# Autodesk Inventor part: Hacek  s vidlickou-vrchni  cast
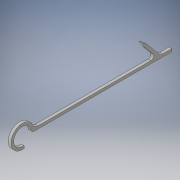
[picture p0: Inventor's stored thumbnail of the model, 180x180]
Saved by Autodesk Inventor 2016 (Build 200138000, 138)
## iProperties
Created: 2015-07
Part Number: Hacek  s vidlickou-vrchni  cast
Material: Generic
Document SubType Name: Modeling
Designer: brecka
Density: 1 g/cm^3
Appearance: Default
Author: brecka
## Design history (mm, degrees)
derived "Hacek  s vidlickou.ipt"
sketch "Náčrt1"
  geometry: L1 (186.029, 3.62)-(199.435, 13.907) reference; L2 (140.971, 3)-(184.202, 3) reference; L3 (123.869, 20.602)-(137.14, 4.786) reference; L4 (118.221, 25)-(123.869, 20.602) reference; L5 (121.571, 18.674)-(118.221, 25) reference; L6 (130.587, 7.928)-(121.571, 18.674) reference; L7 (4.502, 3)-(128.289, 3) reference; L8 (-10.734, -7.851)-(-10.204, -10.804) reference; L9 (184.202, 0)-(0, 0) reference; L10 (199.435, -10.907)-(186.029, -0.62) reference; L11 (199.08, -6.543)-(200.529, -11.436) reference; L12 (191.296, -0.88)-(197.986, -6.014) reference; L13 (197.986, 9.014)-(191.296, 3.88) reference; L14 (200.529, 14.436)-(199.08, 9.543) reference; L15 (150.971, 38)-(170.971, 38); L16 (170.971, 38)-(170.971, -35); L17 (170.971, -35)-(150.971, -35); L18 (150.971, -35)-(150.971, 38); L19 (170.971, 38)-(220.971, 38); L20 (220.971, 38)-(220.971, -35); L21 (220.971, -35)-(170.971, -35); L22 (170.971, -35)-(170.971, 38); L23 (150.971, 38)-(-24.91, 38); L24 (-24.91, 38)-(-24.91, -35); L25 (-24.91, -35)-(150.971, -35); L26 (150.971, -35)-(150.971, 38); A1 r 3 centre (201.262, 11.527) between (200.529, 14.436) and (199.435, 13.907) reference; A2 r 3 centre (184.202, 6) between (184.202, 3) and (186.029, 3.62) reference; A3 r 5 centre (140.971, 8) between (137.14, 4.786) and (140.971, 3) reference; A4 r 3 centre (128.289, 6) between (128.289, 3) and (130.587, 7.928) reference; A5 r 6 centre (4.502, 9) between (-0.983, 6.568) and (4.502, 3) reference; A6 r 12.5 centre (-12.41, 1.5) between (-0.983, 6.568) and (-10.204, -10.804) reference; A7 r 9.5 centre (-12.41, 1.5) between (-2.978, 2.64) and (-10.734, -7.851) reference; A8 r 3 centre (0, 3) between (-2.978, 2.64) and (0, 0) reference; A9 r 3 centre (184.202, -3) between (186.029, -0.62) and (184.202, 0) reference; A10 r 3 centre (201.262, -8.527) between (199.435, -10.907) and (200.529, -11.436) reference; A11 r 3 centre (199.812, -3.633) between (197.986, -6.014) and (199.08, -6.543) reference; A12 r 3 centre (193.122, 1.5) between (191.296, 3.88) and (191.296, -0.88) reference; A13 r 3 centre (199.812, 6.633) between (199.08, 9.543) and (197.986, 9.014) reference; A14 r 12.5 centre (-12.41, 1.5) between (-0.983, 6.568) and (-10.204, -10.804) reference; 1 further point
  constraints: 24 end point, 6 parallel, 3 horizontal, 3 perpendicular, 1 collinear, 1 point on line, 1 tangent
  dimensions: "d1" = 20 distance of L15.start L15.end; "d2" = 10 distance from line of L2.start L18; "d3" = 35 distance between parallel lines of L9 L17; "d4" = 35 distance between parallel lines of L2 L15 (= d3); "d5" = 50 distance between parallel lines of L16 L20
  node "Promítnutá smyčka1"
extrude "Vysunutí1" cut sketch "Náčrt1" stored distance "d6" = 0; taper "d7" = 0 deg
feature "Těleso2::Hacek  s vidlickou.ipt" dims "d0" = 10
tag "Prvek štítků1"
node "Těleso1"
